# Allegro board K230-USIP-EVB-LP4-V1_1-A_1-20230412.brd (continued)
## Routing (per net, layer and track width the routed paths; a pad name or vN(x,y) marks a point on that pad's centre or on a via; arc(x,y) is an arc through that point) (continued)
DQ_B6: length 31.1
  TOP w0.086: v2(32.52,57.28) 32.6,57.28 U7.C4 ; U1.C19 v2(33.13,74.16)
  ART06 w0.086: v2(32.52,57.28) 32.13,57.68 32.13,58.75 31.75,59.13 31.75,62.93 31.84,63.02 32.77,63.02 32.92,63.17 32.92,63.4 32.65,63.67 32.65,65.32 32.49,65.48 31.84,65.48 31.7,65.62 31.7,65.82 31.84,65.96 32.49,65.96 32.63,66.1 32.63,66.3 32.49,66.44 31.84,66.44 31.7,66.58 31.7,66.78 31.84,66.92 32.49,66.92 32.63,67.06 32.63,67.26 32.49,67.4 31.84,67.4 31.7,67.54 31.7,67.74 31.84,67.88 32.49,67.88 32.63,68.02 32.63,68.17 32.49,68.31 31.84,68.31 31.7,68.46 31.7,68.65 31.84,68.79 32.49,68.79 32.63,68.94 32.63,69.18 32.49,69.32 31.74,69.32 31.62,69.44 31.62,69.7 31.73,69.8 32.36,69.8 32.5,69.94 32.5,70.14 32.36,70.28 31.43,70.28 31.29,70.43 31.29,70.62 31.43,70.76 32.23,70.76 32.37,70.91 32.37,71.1 32.23,71.24 31.54,71.24 31.39,71.39 31.39,71.6 31.54,71.74 32.49,71.74 32.63,71.88 32.63,72.3 33.13,72.8 v2(33.13,74.16)
DQ_B7: length 30.9
  TOP w0.086: U7.B4 32.6,57.93 v2(32.52,57.93) ; U1.B19 v2(33.77,74.16)
  ART06 w0.086: v2(32.52,57.93) 32.74,57.93 32.84,58.04 32.84,59.08 32.7,59.22 32.25,59.22 32.11,59.36 32.11,59.56 32.25,59.7 32.7,59.7 32.84,59.84 32.84,60.04 32.7,60.18 32.25,60.18 32.11,60.32 32.11,60.52 32.25,60.66 32.86,60.66 32.97,60.77 32.97,61.07 32.86,61.18 32.26,61.18 32.12,61.32 32.12,61.52 32.26,61.66 33.87,61.66 34.01,61.8 34.01,62 33.87,62.14 32.25,62.14 32.12,62.27 32.12,62.55 32.23,62.66 33.39,62.66 33.53,62.8 33.53,63.52 33.39,63.66 33.17,63.66 33.01,63.82 33.01,65.66 33.15,65.8 33.57,65.8 33.71,65.94 33.71,66.14 33.57,66.28 33.15,66.28 33.01,66.42 33.01,66.62 33.15,66.76 33.46,66.76 33.6,66.9 33.6,67.1 33.46,67.24 33.15,67.24 33.01,67.38 33.01,67.58 33.15,67.72 33.51,67.72 33.66,67.86 33.66,68.06 33.51,68.2 33.15,68.2 33.01,68.34 33.01,70.16 33.15,70.3 33.46,70.3 33.6,70.44 33.6,70.64 33.46,70.78 33.15,70.78 33.01,70.92 33.01,71.12 33.15,71.26 33.46,71.26 33.6,71.4 33.6,71.6 33.46,71.74 33.15,71.74 33.01,71.88 33.01,72.15 33.17,72.31 33.45,72.31 33.58,72.44 33.58,73.2 33.4,73.38 33.4,73.79 v2(33.77,74.16)
DQ_B8: length 35.4
  TOP w0.086: U1.D14 v2(33.13,77.41) ; U7.B11 38.6,57.61 v2(38.93,57.93)
  ART06 w0.086: v2(38.93,57.93) 40,57.93 43.28,61.21 43.28,62.81 45.31,64.85 45.31,67.28 44.17,68.43 44.17,68.73 44.31,68.87 45.15,68.87 45.29,69.01 45.29,69.21 45.15,69.35 44.26,69.35 44.12,69.49 44.12,69.69 44.26,69.83 44.69,69.83 44.83,69.97 44.83,70.17 44.69,70.31 44.31,70.31 44.17,70.45 44.17,70.88 43.97,71.08 43.77,71.08 43.69,70.99 43.49,70.99 43.35,71.13 43.35,71.33 43.43,71.42 43.43,71.62 37.33,77.72 35.56,77.72 35.23,78.05 34.24,78.05 33.92,77.74 33.45,77.74 v2(33.13,77.41)
DQ_B9: length 32.6
  TOP w0.086: U7.C11 38.6,56.96 v2(38.93,57.28) ; v2(36.92,78.04) 36.58,77.7 35.46,77.7 35.42,77.74 U1.A14
  ART06 w0.086: v2(38.93,57.28) 38.93,57.47 39.12,57.66 40.23,57.66 44.06,61.48 44.06,61.68 43.81,61.93 43.81,62.13 43.95,62.27 44.15,62.27 44.4,62.02 44.6,62.02 44.73,62.15 44.73,62.68 44.59,62.82 44.36,62.82 44.25,62.94 44.25,63.19 44.36,63.3 44.59,63.3 44.73,63.45 44.73,63.7 45.67,64.64 45.67,69.89 37.52,78.04 v2(36.92,78.04)
DQ_B10: length 33.7
  TOP w0.086: v2(35.7,78.06) 34.42,78.06 U1.B14 ; U7.E11 38.6,55.66 v2(38.93,55.98)
  ART06 w0.086: v2(35.7,78.06) 35.7,78.27 35.79,78.36 37.71,78.36 46.02,70.04 46.02,64.44 45.11,63.53 45.11,62.03 40.04,56.96 39.33,56.96 39.25,56.87 39.25,56.51 38.93,56.18 v2(38.93,55.98)
DQ_B11: length 35.3
  TOP w0.086: v2(33.78,78.06) 33.77,78.06 U1.C14 ; U7.F11 38.6,55.01 v2(38.93,55.33)
  ART06 w0.086: v2(38.93,55.33) 45.49,61.9 45.49,63.4 46.38,64.29 46.38,70.19 37.86,78.71 34.43,78.71 v2(33.78,78.06)
DQ_B12: length 32.7
  TOP w0.086: v2(37.33,54.68) 37.25,54.68 U7.F9 ; U1.B17 v2(33.77,76.11)
  ART06 w0.086: v2(33.77,76.11) 34.1,75.78 34.95,75.78 36.83,73.9 36.83,68.61 37.19,68.25 37.19,61.57 35.41,59.79 35.41,52.97 35.49,52.88 36.19,52.88 36.33,52.74 36.33,52.59 36.48,52.45 36.7,52.45 36.84,52.59 36.84,52.82 36.98,52.96 37.18,52.96 37.32,52.82 37.32,52.59 37.46,52.45 37.67,52.45 37.77,52.55 37.77,54.56 37.64,54.68 v2(37.33,54.68)
DQ_B13: length 33.8
  TOP w0.086: U7.E9 37,55.66 v2(37.33,55.33) ; U1.C16 v2(33.77,76.76)
  ART06 w0.086: v2(37.33,55.33) 37.33,55.11 37.24,55.02 36.18,55.02 36.09,55.1 36.09,55.58 36.18,55.66 36.87,55.66 36.96,55.75 36.96,59.39 37.78,60.21 39.56,60.21 40.64,61.29 40.64,61.8 38.25,64.19 38.25,68.76 37.9,69.11 37.9,69.85 38.63,70.59 39.6,70.59 39.88,70.87 39.88,72.44 39.01,73.3 38.76,73.3 38.61,73.46 38.61,73.79 36.28,76.11 35.52,76.11 35.19,76.44 34.09,76.44 v2(33.77,76.76)
DQ_B14: length 33.3
  TOP w0.086: v2(36.53,56.63) 36.6,56.63 U7.C9 ; v2(36.39,74.97) 35.57,74.97 U1.A17
  ART06 w0.086: v2(36.53,56.63) 36.25,56.36 35.99,56.36 35.81,56.54 35.81,56.92 36.11,57.21 36.11,58.01 35.81,58.31 35.81,59.69 37.06,60.93 37.43,60.93 37.57,61.08 37.57,61.28 37.71,61.42 38.87,61.42 39.01,61.28 39.01,61.08 39.1,60.99 39.29,60.99 39.6,61.29 39.6,61.8 39.47,61.93 37.69,61.93 37.54,62.08 37.54,68.43 37.19,68.78 37.19,71.75 37.34,71.91 37.54,71.91 37.68,71.77 37.68,71.46 37.76,71.37 38.07,71.37 38.16,71.46 38.16,71.82 38.3,71.96 38.5,71.96 38.63,71.83 38.63,71.46 38.72,71.37 39.03,71.37 39.12,71.46 39.12,72.19 38.91,72.39 38.56,72.39 38.3,72.64 38.08,72.64 37.82,72.39 37.59,72.39 37.19,72.8 37.19,74.17 v2(36.39,74.97)
DQ_B15: length 33.7
  TOP w0.086: U1.B16 v2(34.42,76.11) ; v2(36.53,57.28) 36.6,57.28 U7.B9
  ART06 w0.086: v2(36.53,57.28) 36.6,57.36 36.6,58.01 36.2,58.42 36.2,59.49 36.45,59.74 36.65,59.74 36.8,59.74 36.98,59.92 36.98,60.32 37.23,60.57 37.33,60.57 37.64,60.57 37.87,60.57 38.01,60.71 38.01,60.92 38.15,61.06 38.35,61.06 38.49,60.92 38.49,60.71 38.63,60.57 39.41,60.57 40.28,61.44 40.28,61.62 39.62,62.28 38.97,62.28 38.88,62.37 38.88,63.03 38.74,63.17 38.55,63.17 38.4,63.03 38.4,62.37 38.32,62.28 38,62.28 37.9,62.38 37.9,68.61 37.54,68.96 37.54,70 37.78,70.24 37.78,70.44 37.58,70.63 37.58,70.83 37.72,70.97 37.92,70.97 38.12,70.78 38.32,70.78 38.48,70.94 39.41,70.94 39.5,71.03 39.5,72.31 38.89,72.92 38.55,72.92 38.27,73.2 38.07,73.2 37.79,72.92 37.67,72.92 37.54,73.05 37.54,73.4 37.85,73.7 37.85,74.04 36.11,75.78 35.4,75.78 35.07,76.11 v2(34.42,76.11)
DQS0_C_A: length 30.7
  TOP w0.076: U1.Y17 22.19,75.79 22.08,75.67 v2(22.08,75.46)
  TOP w0.089: v2(19.02,55.98) 19.02,55.78 19.14,55.66 U5.E3
  ART06 w0.089: v2(22.08,75.46) 22.06,75.48 21.76,75.48 20.3,74.02 19.53,74.02 16.04,70.53 16.04,70.1 15.88,69.94 15.42,69.94 15.06,69.58 15.06,69.08 15.42,68.72 15.88,68.72 17.42,67.18 17.42,64.8 15.8,63.17 14.71,63.17 14.31,62.78 14.31,61.66 16.76,59.21 18.01,59.21 18.67,58.54 18.67,56.82 19.28,56.2 19.28,56.08 19.19,55.98 v2(19.02,55.98)
DQS0_C_B: length 31.1
  TOP w0.089: U1.A18 34.75,75.13 v2(34.43,74.81) ; U7.E3 32.05,55.66 v2(31.72,55.98)
  ART06 w0.089: v2(34.43,74.81) 34.43,74.52 34.54,74.4 34.54,73.9 34.7,73.75 35.03,73.75 35.38,73.39 35.38,72.88 35.03,72.53 34.7,72.53 34.54,72.38 34.54,72.15 34.7,71.99 35.03,71.99 35.38,71.64 35.38,71.13 35.03,70.78 34.7,70.78 34.54,70.62 34.54,70.39 34.7,70.24 35.03,70.24 35.38,69.89 35.38,69.38 35.03,69.02 34.7,69.02 34.54,68.87 34.54,68.64 34.7,68.49 35.03,68.49 35.38,68.14 35.38,67.62 35.03,67.27 34.7,67.27 34.54,67.12 34.54,66.89 34.7,66.74 35.16,66.74 35.48,66.41 35.48,65.9 35.11,65.52 34.7,65.52 34.54,65.37 34.54,65.14 34.7,64.98 35.36,64.98 35.71,64.63 35.71,64.12 35.36,63.76 34.7,63.76 34.54,63.61 34.54,63.29 34.7,63.14 35.39,63.14 35.75,62.78 35.75,62.19 33.78,60.22 33.78,56.21 33.29,55.71 32.32,55.71 32.05,55.98 v2(31.72,55.98)
DQS0_T_A: length 30.6
  TOP w0.076: U1.W17 v2(22.73,75.46)
  TOP w0.089: v2(19.82,55.98) 19.5,56.31 U5.D3
  ART06 w0.089: v2(22.73,75.46) 22.4,75.13 21.9,75.13 20.44,73.68 19.68,73.68 16.38,70.38 16.38,69.95 16.03,69.6 15.56,69.6 15.41,69.44 15.41,69.22 15.56,69.06 16.03,69.06 17.77,67.32 17.77,64.65 15.94,62.83 14.85,62.83 14.66,62.63 14.66,61.8 16.91,59.55 18.15,59.55 19.01,58.69 19.01,56.96 19.63,56.35 19.63,56.18 v2(19.82,55.98)
DQS0_T_B: length 31.3
  TOP w0.089: U1.B18 v2(33.78,74.81) ; v2(31.72,56.63) 32.05,56.31 U7.D3
  ART06 w0.089: v2(33.78,74.81) 34.08,74.5 34.08,74.38 34.2,74.26 34.2,73.76 34.55,73.4 34.89,73.4 35.04,73.25 35.04,73.02 34.89,72.87 34.55,72.87 34.2,72.52 34.2,72 34.55,71.65 34.89,71.65 35.04,71.5 35.04,71.27 34.89,71.12 34.55,71.12 34.2,70.77 34.2,70.25 34.55,69.9 34.89,69.9 35.04,69.75 35.04,69.52 34.89,69.37 34.55,69.37 34.2,69.01 34.2,68.5 34.55,68.15 34.89,68.15 35.04,67.99 35.04,67.77 34.89,67.61 34.55,67.61 34.2,67.26 34.2,66.75 34.55,66.39 35.01,66.39 35.14,66.27 35.14,66.04 34.96,65.86 34.55,65.86 34.2,65.51 34.2,64.99 34.55,64.64 35.22,64.64 35.37,64.49 35.37,64.26 35.22,64.11 34.55,64.11 34.2,63.75 34.2,63.15 34.55,62.79 35.25,62.79 35.41,62.63 35.41,62.33 33.44,60.36 33.44,57.33 33.33,57.22 33.23,57.22 33.12,57.12 33.12,56.97 33.23,56.87 33.33,56.87 33.44,56.76 33.44,56.35 33.15,56.06 32.46,56.06 32.19,56.33 31.89,56.33 31.72,56.49 v2(31.72,56.63)
DQS1_C_A: length 29.5
  TOP w0.089: v2(25.43,55.98) 25.1,55.66 U5.E10 ; U1.V19 v2(24.03,74.16)
  ART06 w0.089: v2(25.43,55.98) 25.12,55.98 24.79,56.31 23.67,56.31 23.48,56.5 23.48,61.19 23.13,61.54 22.7,61.54 22.54,61.7 22.54,61.92 22.7,62.08 23.13,62.08 23.48,62.44 23.48,62.94 23.13,63.3 22.7,63.3 22.54,63.45 22.54,63.67 22.7,63.83 23.13,63.83 23.48,64.19 23.48,64.69 23.13,65.05 22.7,65.05 22.54,65.21 22.54,65.43 22.7,65.58 23.13,65.58 23.48,65.94 23.48,66.45 23.13,66.8 22.7,66.8 22.54,66.96 22.54,67.18 22.7,67.34 23.13,67.34 23.48,67.69 23.48,68.2 23.13,68.56 22.7,68.56 22.54,68.71 22.54,68.93 22.7,69.09 23.13,69.09 23.48,69.45 23.48,69.95 23.13,70.31 22.7,70.31 22.54,70.46 22.54,70.69 22.7,70.84 23.95,70.84 24.35,71.23 24.35,73.84 v2(24.03,74.16)
DQS1_C_B: length 33.3
  TOP w0.089: U7.E10 37.8,55.66 v2(38.13,55.98) ; U1.A15 v2(34.42,77.41)
  ART06 w0.089: v2(34.42,77.41) 35.04,77.41 35.32,77.13 36.54,77.13 40.82,72.85 40.82,71.7 40.99,71.54 41.49,71.54 41.87,71.16 41.87,70.47 41.51,70.11 40.63,70.11 40.51,70 40.51,68.91 39.22,67.61 39.22,64.57 41.11,62.67 41.82,62.67 42.21,62.28 42.21,61.52 39.68,58.98 37.9,58.98 37.76,58.84 37.76,57.09 38.25,56.59 38.25,56.11 v2(38.13,55.98)
DQS1_T_A: length 29.1
  TOP w0.089: U1.V20 v2(24.03,73.51) ; v2(24.63,55.98) 24.95,56.31 U5.D10
  ART06 w0.089: v2(24.03,73.51) 24,73.49 24,73.42 23.9,73.32 23.78,73.32 23.67,73.21 23.67,73.06 23.78,72.96 23.9,72.96 24,72.86 24,71.38 23.81,71.18 22.56,71.18 22.2,70.83 22.2,70.32 22.56,69.97 22.98,69.97 23.14,69.81 23.14,69.59 22.98,69.43 22.56,69.43 22.2,69.07 22.2,68.57 22.56,68.21 22.98,68.21 23.14,68.06 23.14,67.84 22.98,67.68 22.56,67.68 22.2,67.32 22.2,66.82 22.56,66.46 22.98,66.46 23.14,66.3 23.14,66.08 22.98,65.93 22.56,65.93 22.2,65.57 22.2,65.06 22.56,64.71 22.98,64.71 23.14,64.55 23.14,64.33 22.98,64.17 22.56,64.17 22.2,63.82 22.2,63.31 22.56,62.95 22.98,62.95 23.14,62.8 23.14,62.58 22.98,62.42 22.56,62.42 22.2,62.06 22.2,61.56 22.56,61.2 22.98,61.2 23.14,61.05 23.14,56.36 23.53,55.97 23.84,55.97 23.95,55.86 23.95,55.76 24.05,55.65 24.2,55.65 24.3,55.76 24.3,55.86 24.41,55.97 24.61,55.97 v2(24.63,55.98)
DQS1_T_B: length 33.5
  TOP w0.089: U7.D10 37.65,56.31 v2(37.33,55.98) ; U1.B15 v2(34.43,76.76)
  ART06 w0.089: v2(34.43,76.76) 34.43,76.98 34.51,77.07 34.9,77.07 35.18,76.78 36.4,76.78 40.47,72.7 40.47,71.56 40.84,71.19 41.35,71.19 41.53,71.02 41.53,70.61 41.37,70.46 40.48,70.46 40.17,70.14 40.17,69.05 38.87,67.76 38.87,64.42 40.97,62.33 41.68,62.33 41.87,62.14 41.87,61.66 39.54,59.32 39.03,59.32 38.79,59.56 38.43,59.56 38.19,59.32 37.75,59.32 37.41,58.98 37.41,56.95 37.91,56.45 37.91,56.32 37.57,55.98 v2(37.33,55.98)
EMMC_CLK: length 36.7
  TOP w0.127: U1.A5 37.74,83.59 v2(38.1,83.95)
  BOTTOM w0.127: R50.1 38.73,109.35 41.4,106.68 41.4,94.13 41.25,93.99 40.53,93.99 40.39,93.84 40.39,93.63 40.53,93.48 41.25,93.48 41.4,93.33 41.4,93.12 41.25,92.97 40.53,92.97 40.39,92.82 40.39,92.61 40.53,92.46 41.25,92.46 41.4,92.31 41.4,92.02 41.25,91.87 40.56,91.87 40.39,91.69 40.39,88.14 38.48,86.23 38.48,84.33 v2(38.1,83.95)
EMMC_CMD: length 43
  TOP w0.127: v2(43.16,114.81) U30.M5 ; U1.D6 v2(33.12,83.26)
  BOTTOM w0.076: v2(33.12,83.26) 33.45,83.58 34.03,83.58
  BOTTOM w0.127: v2(43.16,114.81) 42.65,115.32 42.29,115.32 42.16,115.19 42.16,113.66 41.66,113.16 38.23,113.16 37.47,112.39 R48.1 37.97,111.89 38.1,111.76 38.1,109.35 39.12,108.33 39.12,103.12 38.1,102.11 38.1,97.03 35.69,94.61 35.69,89.66 36.45,88.9 36.45,85.09 34.94,83.58 34.03,83.58
EMMC_D0: length 43
  TOP w0.127: U1.D5 v2(33.12,83.91) ; U30.A3 44.16,109.13 44.32,108.97 44.32,107.19 42.55,105.41 39.75,105.41 38.73,104.39 38.73,104.01 v1(38.1,103.38)
  BOTTOM w0.076: v2(33.12,83.91) 33.45,84.23 34.03,84.23
  BOTTOM w0.127: v1(38.1,103.38) 37.34,102.62 37.34,97.28 34.16,94.11 32.03,94.11 31.88,93.95 31.88,93.74 32.03,93.59 32.89,93.59 33.02,93.46 33.02,93.19 32.89,93.07 32.03,93.07 31.88,92.91 31.88,92.7 32.03,92.54 32.99,92.54 33.15,92.39 33.15,92.18 32.99,92.02 32.03,92.02 31.88,91.87 31.88,91.66 32.03,91.5 32.99,91.5 33.15,91.35 33.15,90.3 33.27,90.17 34.8,90.17 34.92,90.04 34.92,89.03 35.43,88.52 35.43,85.34 34.32,84.23 34.03,84.23
EMMC_D1: length 43.1
  TOP w0.127: U30.A4 43.66,108.68 43.31,108.33 43.31,107.31 41.78,105.79 39.5,105.79 v1(38.1,104.39) ; U1.C5 v2(33.77,83.91)
  BOTTOM w0.127: v1(38.1,104.39) 38.61,104.39 38.73,104.27 38.73,103.25 37.72,102.23 37.72,97.16 35.31,94.74 35.31,93.62 35.15,93.46 33.68,93.46 33.53,93.31 33.53,93.1 33.68,92.94 35.15,92.94 35.31,92.79 35.31,92.58 35.15,92.42 33.68,92.42 33.53,92.27 33.53,92.05 33.68,91.9 35.15,91.9 35.31,91.75 35.31,91.53 35.15,91.38 33.68,91.38 33.53,91.23 33.53,91.01 33.68,90.86 35.15,90.86 35.31,90.71 35.31,89.41 35.94,88.77 35.94,85.34 34.51,83.91 v2(33.77,83.91)
EMMC_D2: length 43
  TOP w0.076: 35.05,83.91 34.42,83.91 U1.B5
  TOP w0.127: v2(38.1,84.71) 37.3,83.91 35.05,83.91 ; v1(40.64,106.55) 42.67,108.58 43.16,109.07 U30.A5
  BOTTOM w0.127: v1(40.64,106.55) 40.89,106.3 40.89,101.04 40.75,100.89 40.15,100.89 40.01,100.74 40.01,100.53 40.15,100.38 40.75,100.38 40.89,100.23 40.89,100.02 40.75,99.87 39.9,99.87 39.75,99.72 39.75,99.51 39.9,99.36 40.75,99.36 40.89,99.21 40.89,99 40.75,98.86 39.9,98.86 39.75,98.71 39.75,98.5 39.9,98.35 40.75,98.35 40.89,98.2 40.89,97.99 40.75,97.84 39.9,97.84 39.75,97.69 39.75,97.48 39.9,97.33 40.75,97.33 40.89,97.18 40.89,96.97 40.75,96.82 39.9,96.82 39.75,96.67 39.75,96.46 39.9,96.32 40.75,96.32 40.89,96.17 40.89,95.89 40.77,95.76 40.05,95.76 39.93,95.63 39.93,95.32 40.08,95.17 40.75,95.17 40.89,95.02 40.89,94.81 40.75,94.66 40.08,94.66 39.75,94.33 39.75,88.27 38.1,86.61 v2(38.1,84.71)
EMMC_D3: length 43
  TOP w0.076: 44.91,109.47 44.91,110.03 U30.B2
  TOP w0.127: v1(39.62,103.5) 41.91,103.5 45.09,106.68 45.09,109.09 44.91,109.27 44.91,109.47 ; U1.C6 v2(33.77,83.26)
  BOTTOM w0.127: v1(39.62,103.5) 39.62,103.12 38.48,101.98 38.48,96.9 37.08,95.5 37.08,94.67 36.93,94.52 36.22,94.52 36.07,94.37 36.07,94.15 36.22,94 37.06,94 37.21,93.85 37.21,93.63 37.06,93.48 36.22,93.48 36.07,93.33 36.07,93.11 36.22,92.96 36.93,92.96 37.08,92.81 37.08,92.59 36.93,92.44 36.22,92.44 36.07,92.29 36.07,92.07 36.22,91.92 36.93,91.92 37.08,91.77 37.08,91.55 36.93,91.4 36.22,91.4 36.07,91.25 36.07,91.03 36.22,90.88 36.93,90.88 37.08,90.72 37.08,90.51 36.93,90.36 36.22,90.36 36.07,90.2 36.07,89.99 36.22,89.84 36.83,89.84 36.96,89.71 36.96,84.96 35.25,83.26 v2(33.77,83.26)
EMMC_D4: length 43.3
  TOP w0.076: U30.B3 44.41,110.03 44.41,109.47
  TOP w0.127: v1(39.62,104.52) 42.29,104.52 44.7,106.93 44.7,108.97 44.41,109.26 44.41,109.47 ; U1.D7 v2(33.12,82.61)
  BOTTOM w0.076: 34.03,82.93 33.45,82.93 v2(33.12,82.61)
  BOTTOM w0.127: v1(39.62,104.52) 40.13,104.01 40.13,102.11 39.86,101.83 39.64,101.83 39.48,102 39.26,102 39.11,101.85 39.11,101.63 39.27,101.46 39.27,101.25 38.86,100.84 38.86,96.65 37.64,95.43 37.64,93.98 37.8,93.83 37.95,93.83 38.1,93.68 38.1,93.46 37.95,93.31 37.67,93.31 37.52,93.16 37.52,92.94 37.67,92.79 37.95,92.79 38.1,92.64 38.1,92.42 37.95,92.27 37.67,92.27 37.52,92.12 37.52,91.9 37.67,91.75 37.95,91.75 38.1,91.6 38.1,91.38 37.95,91.23 37.67,91.23 37.52,91.08 37.52,90.84 37.66,90.69 37.95,90.69 38.1,90.54 38.1,90.33 37.95,90.18 37.66,90.18 37.52,90.03 37.52,89.82 37.67,89.67 38.2,89.67 38.35,89.51 38.35,89.3 38.2,89.14 37.59,89.14 37.47,89.02 37.47,88.75 37.59,88.62 38.33,88.62 38.48,88.47 38.48,88.26 38.33,88.1 37.54,88.1 37.34,87.9 37.34,84.71 35.56,82.93 34.03,82.93
EMMC_D5: length 42.8
  TOP w0.076: 43.91,109.24 43.91,110.03 U30.B4
  TOP w0.127: U1.A7 35.55,82.29 35.61,82.35 38.79,82.35 39.26,82.82 39.51,82.82 v2(39.75,83.06) ; 43.91,109.24 43.91,107.66 v1(43.81,107.57)
  BOTTOM w0.127: v2(39.75,83.06) 40.13,83.44 40.13,85.22 41.27,86.36 42.16,86.36 43.43,87.63 43.43,101.98 43.56,102.11 45.19,102.11 45.34,102.26 45.34,102.48 45.19,102.63 43.59,102.63 43.43,102.78 43.43,103 43.59,103.15 45.19,103.15 45.34,103.3 45.34,103.52 45.19,103.67 44.58,103.67 44.45,103.8 44.45,104.06 44.58,104.19 45.19,104.19 45.34,104.34 45.34,107.44 45.21,107.57 v1(43.81,107.57)
EMMC_D6: length 43.1
  TOP w0.076: 43.41,109.24 43.41,110.03 U30.B5 ; 35.05,82.61 34.42,82.61 U1.B7
  TOP w0.127: 35.05,82.61 38.54,82.61 39.5,83.57 v2(39.5,83.95) ; 43.41,109.24 43.41,108.94 42.8,108.33 v1(42.8,107.7)
  BOTTOM w0.127: v1(42.8,107.7) 43.05,107.44 43.05,106.49 43.21,106.34 44.68,106.34 44.83,106.19 44.83,105.97 44.68,105.82 43.21,105.82 43.05,105.67 43.05,105.45 43.21,105.3 44.68,105.3 44.83,105.15 44.83,104.93 44.68,104.78 43.21,104.78 43.05,104.63 43.05,104.37 43.2,104.22 43.92,104.22 44.07,104.07 44.07,103.86 43.92,103.71 43.2,103.71 43.05,103.56 43.05,88.01 41.78,86.74 41.02,86.74 39.75,85.47 39.75,84.2 v2(39.5,83.95)
EMMC_D7: length 43
  TOP w0.076: U30.B6 42.91,110.03 42.91,109.47
  TOP w0.127: 42.91,109.47 42.91,109.33 42.42,108.84 42.04,108.84 v1(39.75,106.55) ; U1.C7 v2(33.77,82.61)
  BOTTOM w0.127: v1(39.75,106.55) 40.51,105.79 40.51,101.85 39.24,100.58 39.24,95.98 39.09,95.83 38.76,95.83 38.61,95.68 38.61,95.47 38.76,95.33 39.35,95.33 39.5,95.18 39.5,94.97 39.35,94.82 38.38,94.82 38.23,94.67 38.23,94.46 38.38,94.31 39.09,94.31 39.24,94.16 39.24,93.95 39.09,93.8 38.76,93.8 38.61,93.65 38.61,93.44 38.76,93.29 39.09,93.29 39.24,93.14 39.24,92.93 39.09,92.79 38.76,92.79 38.61,92.64 38.61,92.43 38.76,92.28 39.09,92.28 39.24,92.13 39.24,91.92 39.09,91.77 38.76,91.77 38.61,91.62 38.61,91.41 38.76,91.26 39.09,91.26 39.24,91.11 39.24,90.9 39.09,90.75 38.73,90.75 38.61,90.63 38.61,90.37 38.73,90.25 39.09,90.25 39.24,90.1 39.24,89.72 39.09,89.57 38.88,89.57 38.73,89.42 38.73,89.21 38.88,89.06 39.09,89.06 39.24,88.91 39.24,88.39 38.48,87.63 37.85,87.63 37.72,87.5 37.72,84.33 36.8,83.41 36.8,83.2 37.06,82.94 37.06,82.73 36.91,82.58 36.7,82.58 36.44,82.84 36.23,82.84 36.05,82.66 33.83,82.66 v2(33.77,82.61)
EMMC_RST: length 41.4
  TOP w0.127: U30.K5 v2(43.67,114.28) ; U1.A6 38.32,82.94 38.86,83.48 v2(38.86,83.99)
  BOTTOM w0.127: v2(38.86,83.99) 39.24,84.37 39.24,85.72 40.77,87.25 41.66,87.25 42.49,88.09 42.49,107.11 42.16,107.44 42.16,108.08 44.96,110.87 44.96,112.99 v2(43.67,114.28) R49.1 C25.1
EMMC_STROBE: length 40.1
  TOP w0.076: 34.92,83.26 34.42,83.26 U1.B6
  TOP w0.127: 34.92,83.26 38.05,83.26 38.48,83.69 38.48,84.33 v2(38.86,84.71)
  BOTTOM w0.127: R47.1 R59.1 40.01,108.84 40.47,108.37 40.69,108.37 41.17,108.85 41.39,108.85 41.54,108.7 41.54,108.49 41.06,108 41.06,107.79 41.91,106.93 41.91,91.31 41.78,91.19 41.15,91.19 41.02,91.06 41.02,90.91 41.17,90.76 41.76,90.76 41.91,90.61 41.91,90.4 41.76,90.25 41.17,90.25 41.02,90.1 41.02,89.89 41.17,89.75 41.76,89.75 41.91,89.6 41.91,89.39 41.76,89.24 41.17,89.24 41.02,89.09 41.02,88.14 38.86,85.98 v2(38.86,84.71)
FT_12MHZ_IN: length 8.2
  TOP w0.254: Y5.3 67.95,100.36 67.95,102 C201.1 67.89,102.7 67.89,103.69 66.35,105.23 U26.2
FT_12MHZ_OUT: length 7.2
  TOP w0.254: U26.3 66.48,105.73 68.39,103.83 68.39,102.71 C204.1 68.46,102.13 68.46,101.36 Y5.1
FTVCC_1V8: length 32.2
  TOP w0.254: v1(56.52,102.76) 56.96,103.2 U26.49 ; U26.64 v1(64.46,102.62) ; U26.12 66.15,110.23 v1(66.43,110.51) ; U26.37 v1(55.13,110.23)
  BOTTOM w0.381: v1(56.52,102.76) 56.65,102.89 C202.2 55.63,103.65 54.48,104.8 54.48,109.59 v1(55.13,110.23) 55.28,110.38 C221.2 ; C222.2 C220.2 ; C222.2 63.51,102.81 ; C222.2 68.09,103.65 69.34,104.9 69.34,109.86 68.69,110.51 v1(66.43,110.51) C199.2
FTVCC_3V3: length 21.4
  TOP w0.203: v1(53.72,110.87) 53.41,110.56 U36.1
  TOP w0.254: v1(57.74,102.76) 57.46,103.04 U26.50 ; U26.56 v1(60.46,102.77) ; v1(62.62,114.07) 62.96,113.72 U26.20 ; U26.31 v1(57.46,113.91) ; U26.42 v1(55.13,107.73)
  TOP w0.305: C368.1 53.98,111.12 v1(53.72,110.87)
  TOP w0.381: v1(64.77,98.17) R205.1 R204.1 R203.1 ; R201.1 v1(68.45,112.78)
  BOTTOM w0.305: C200.2 57.54,113.84 v1(57.46,113.91) ; v1(55.13,107.73) 55.24,107.84 C219.2 ; C203.2 v1(62.62,114.07)
  BOTTOM w0.381: v1(57.74,102.76) 57.54,102.97 C217.2 C216.2 ; FB7.1 v1(68.46,107.7) FB8.1 ; v1(60.46,102.77) 60.46,102.77 C218.2
  vias: v1(63.5,98.17) v1(69.72,112.78) v1(70.99,112.78)
G0: length 5.4
  TOP w0.127: TP28.1 R133.1 R131.1 57.02,125.73 57.42,125.33 U16.15
GPIO9: length 1.8
  TOP w0.127: R184.2 v1(9.02,81.92)
  BOTTOM w0.127: R184.2 v1(9.02,81.92)
GPIO26: length 6.6
  TOP w0.127: R91.1 5.08,27.94 3.17,27.94 J8.1
GPIO27: length 129.4
  TOP w0.127: R93.1 v1(6.22,73.91) ; v3(41.53,131.57) 41.26,131.85 J3.36
  ART06 w0.127: J8.2 3.43,30.23 3.43,47.24 4.39,48.21 4.39,53.49 5.73,54.83 5.73,73.42 v1(6.22,73.91) 6.73,74.42 6.73,75.44 5.73,76.44 5.73,77.74 7.23,79.24 7.23,84.52 8.36,85.65 12.88,85.65 20.83,93.6 20.83,117.73 33.15,130.05 40.01,130.05 v3(41.53,131.57)
GPIO28: length 132.2
  TOP w0.127: v3(42.67,132.59) 42.76,132.67 J3.42 ; R95.1 v1(6.22,75.06)
  ART06 w0.127: v3(42.67,132.59) 42.16,132.08 40.13,132.08 39.12,131.06 32.64,131.06 19.81,118.24 19.81,96.01 10.46,86.66 7.92,86.66 5.42,84.16 5.42,75.86 v1(6.22,75.06) 5.44,74.27 5.44,54.94 4.11,53.62 4.11,48.56 3.05,47.5 3.05,27.81 1.91,26.67
GPIO29: length 62.6
  TOP w0.127: R182.2 v1(8.89,84.45)
  ART06 w0.127: J8.4 5.46,27.69 5.46,29.84 3.71,31.6 3.71,47.02 4.7,48.01 4.7,53.37 6.02,54.69 6.02,69.09 8.08,71.15 8.08,83.64 v1(8.89,84.45)
  BOTTOM w0.127: R182.2 v1(8.89,84.45)
GPIO30: length 66.1
  TOP w0.127: R183.2 v1(8.89,83.19)
  ART06 w0.127: 1.91,24.13 3.17,25.4 5.08,25.4 5.84,26.16 5.84,29.97 3.99,31.83 3.99,46.66 5.08,47.75 5.08,53.34 6.3,54.56 6.3,68.96 8.38,71.04 8.38,82.68 v1(8.89,83.19)
  BOTTOM w0.127: R183.2 v1(8.89,83.19)
GPIO31: length 64.2
  TOP w0.127: R208.2 v1(8.89,80.77)
  ART06 w0.127: v1(8.89,80.77) 8.79,80.67 8.79,71.02 6.58,68.81 6.58,54.43 5.46,53.31 5.46,47.62 4.27,46.43 4.27,32.05 6.22,30.1 6.22,23.37 J8.8
  BOTTOM w0.127: R208.2 v1(8.89,80.77)
GPIO32: length 2.7
  TOP w0.127: R103.1 J8.6
GPIO33: length 6.2
  TOP w0.127: R105.1 5.97,22.73 3.05,22.73 1.91,21.59
GPIO34: length 6.3
  TOP w0.127: 1.91,19.05 3.17,20.32 5.84,20.32 R107.1
GPIO35: length 6.2
  TOP w0.127: 1.91,16.51 3.05,17.65 5.97,17.65 R109.1
GPIO36: length 6.2
  TOP w0.127: 1.91,13.97 3.05,15.11 5.97,15.11 R111.1
GPIO37: length 6.2
  TOP w0.127: 1.91,11.43 3.05,12.57 5.97,12.57 R113.1
GPIO42: length 36.2
  TOP w0.127: v1(36.83,104.14) 36.83,100.08 R100.2
  ART06 w0.127: v1(36.83,104.14) 37.21,104.52 37.21,117.86 47.16,127.8 v3(47.37,127.8)
  BOTTOM w0.127: R181.2 46.86,129.41 46.86,128.31 v3(47.37,127.8)
GPIO43: length 56.6
  TOP w0.127: R102.2 v1(49.28,84.07)
  ART06 w0.127: v3(49.4,127.8) 51.18,126.02 51.18,122.3 48.01,119.13 48.01,104.78 50.42,102.36 v1(51.18,102.36)
  BOTTOM w0.127: v1(49.28,84.07) 49.78,84.58 49.78,92.71 53.09,96.01 53.09,99.57 51.94,100.71 51.94,101.6 v1(51.18,102.36) ; R180.2 45.21,129.16 47.12,127.25 48.86,127.25 v3(49.4,127.8)
GPIO46: length 35.8
  ART06 w0.127: v1(38.1,105.41) 37.59,105.92 37.59,117.6 43.43,123.44 v1(44.58,123.44)
  BOTTOM w0.127: v1(44.58,123.44) 45.09,123.95 45.09,128.64 R179.2 ; R108.2 36.83,102.87 37.47,103.5 37.47,104.78 v1(38.1,105.41)
GPIO47: length 47.9
  TOP w0.127: J3.30 39.75,134.87 39.5,135.13 v3(39.24,135.13)
  ART06 w0.127: v3(39.24,135.13) 40.89,133.48 43.56,133.48 44.45,132.59 44.45,127 34.92,117.47 v1(34.92,109.73)
  BOTTOM w0.127: v1(34.92,109.73) 32,106.81 31.24,106.81 30.61,106.17 30.61,99.44 R110.2
GPIO48: length 46.6
  TOP w0.127: v3(40.13,135.06) 40.25,134.94 J3.32
  ART06 w0.127: v3(40.13,135.06) 41.4,133.79 43.88,133.79 44.83,132.84 44.83,126.75 35.56,117.47 35.56,107.19 v1(36.32,106.43)
  BOTTOM w0.127: R112.2 33.4,103.38 33.91,103.89 33.91,104.9 35.43,106.43 v1(36.32,106.43)
GPIO49: length 45.3
  TOP w0.127: J3.34 40.76,134.93 40.88,135.06 v3(40.89,135.06)
  ART06 w0.127: v1(36.32,107.44) 35.94,107.82 35.94,117.22 45.21,126.49 45.21,132.97 44.07,134.11 41.84,134.11 v3(40.89,135.06)
  BOTTOM w0.127: R114.2 35.69,103 36.32,103.63 36.32,104.65 37.08,105.41 37.08,106.68 v1(36.32,107.44)
GPIO52: length 104.3
  TOP w0.127: v1(51.31,107.19) 51.82,107.7 51.82,108.2 51.98,108.37 U36.6
  ART06 w0.127: v1(27.94,114.3) 26.16,114.3 25.4,113.54 25.4,103.63 v1(26.42,102.62)
  BOTTOM w0.127: v1(27.94,114.3) 31.11,117.47 45.34,117.47 48.9,113.92 48.9,109.6 v1(51.31,107.19) ; R119.1 26.42,102.49 v1(26.42,102.62) 23.24,102.62 19.37,98.74 19.37,79.69 10.79,71.12 5.97,71.12 5.45,71.63 5.45,73.92 J5.4 J5.2
GPIO53: length 137.7
  TOP w0.127: U36.5 51.74,108.77 v1(51.31,108.33)
  ART06 w0.127: v1(26.42,101.6) 25.02,103 25.02,113.86 26.48,115.32 v1(27.94,115.32) ; v1(74.42,84.45) 73.28,85.6 73.28,87.38 68.71,91.95 67.82,91.95 60.71,99.06 58.55,99.06 51.94,105.66 51.94,107.7 v1(51.31,108.33)
  BOTTOM w0.127: v1(51.31,108.33) 49.66,109.98 49.66,113.73 45.5,117.88 30.89,117.88 28.32,115.32 v1(27.94,115.32) ; v1(74.42,84.45) TVS12.1 73.55,83.58 R194.2 R55.2 ; J5.6 4.45,71.5 5.33,70.61 10.8,70.61 19.81,79.63 19.81,98.42 22.99,101.6 v1(26.42,101.6) 27.18,100.84 27.18,100.58 R120.1
GPIO60_3V3: length 69.6
  TOP w0.127: U25.12 69.3,118.19 v1(69.85,118.75) R242.2
  ART06 w0.127: v1(24.26,99.82) 23.5,100.58 23.5,114.94 v1(27.94,119.38)
  BOTTOM w0.127: R127.1 v1(24.26,99.82) ; v1(27.94,119.38) 27.94,119.38 46.48,119.38 49.02,116.84 63.88,116.84 64.52,116.2 65.79,116.2 68.33,118.75 v1(69.85,118.75)
GPIO61_3V3: length 69.1
  TOP w0.127: R243.2 70.1,116.97 v1(69.85,116.97) 69.47,116.97 68.64,117.79 U25.11
  ART06 w0.127: v1(27.94,118.37) 27.56,118.37 23.88,114.68 23.88,101.35 v1(25.4,99.82)
  BOTTOM w0.127: v1(69.85,116.97) 67.06,116.97 65.79,115.7 64.39,115.7 63.75,116.33 48.77,116.33 46.07,119.03 28.61,119.03 v1(27.94,118.37) ; v1(25.4,99.82) R128.1
HP_INSERT_DET: length 5.7
  TOP w0.127: J7.6 v1(76.2,124.33)
  BOTTOM w0.127: v1(76.2,124.33) 76.2,124.32 R35.2 ; R35.2 R221.2 ; R35.2 C162.1
HP_L: length 39.2
  TOP w0.127: J20.3 54.23,101.35 49.02,106.55 49.02,112.78 v1(51.05,114.81)
  ART06 w0.127: v1(66.55,122.56) 65.15,121.16 63.5,121.16 60.83,118.49 54.74,118.49 v1(51.05,114.81)
  BOTTOM w0.127: C159.1 v1(66.55,122.56)
HP_R: length 52.5
  TOP w0.127: J21.3 55.24,97.54 55.24,100.84 49.53,106.55 49.53,112.14 v1(51.05,113.67)
  ART06 w0.127: v1(51.05,113.67) 54.99,117.6 62.74,117.6 65.41,120.27 69.6,120.27 73.15,123.83 v1(73.15,126.11)
  BOTTOM w0.127: v1(73.15,126.11) 74.42,127.38 C161.1
HPOUTL: length 29.6
  TOP w0.127: U1.G1 30.85,88.89 43.31,101.35 v1(46.08,101.35)
  BOTTOM w0.127: J20.2 49.4,101.35 v1(46.08,101.35)
HPOUTR: length 31.3
  TOP w0.076: 31.18,86.47 31.18,85.86 U1.G2
  TOP w0.127: v1(46.08,100.33) 42.8,100.33 31.18,88.71 31.18,86.47
  BOTTOM w0.127: v1(46.08,100.33) 49.78,100.33 50.55,99.57 50.55,97.66 J21.2
HSY0: length 6.5
  TOP w0.127: J3.51 45.26,128.48 46.74,127 47.37,127 R51.2 R53.1
I2C0_SCL_1V8: length 75.2
  TOP w0.127: U25.3 64.16,118.19 63.1,117.13 63.1,115.86 62.32,115.08 56.37,115.08 v1(51.91,119.54) ; v3(41.66,135.06) 41.76,134.96 J3.38
  ART06 w0.127: v3(41.66,135.06) 42.31,134.4 45.81,134.4 53.09,127.13 53.09,120.72 v1(51.91,119.54)
  BOTTOM w0.127: J16.1 16.76,135.64 41.08,135.64 v3(41.66,135.06) 42.16,134.55 42.16,131.56 R234.2
I2C0_SDA_1V8: length 75.1
  TOP w0.127: U25.4 64.33,117.79 63.5,116.97 63.5,115.7 62.48,114.68 55.79,114.68 v1(51.93,118.55) ; J3.40 42.26,134.95 v3(42.42,135.12)
  ART06 w0.127: v1(51.93,118.55) 53.47,120.09 53.47,127.25 46,134.72 42.81,134.72 v3(42.42,135.12)
  BOTTOM w0.127: R235.2 43.31,131.43 43.31,134.23 v3(42.42,135.12) 42.42,136.53 42.04,136.91 18.03,136.91 J16.2
I2C1_SCL: length 40.4
  TOP w0.127: R240.2 43.92,128.17 v1(43.56,128.17) 43.26,128.47 J3.43 ; v1(35.81,104.2) 35.81,100.2 R96.2
  ART06 w0.127: v1(35.81,104.2) 33.66,106.36 33.66,119.13 42.7,128.17 v1(43.56,128.17)
I2C1_SDA: length 41.6
  TOP w0.127: J3.45 43.76,129.13 v1(43.94,128.94) 44.28,128.94 R241.2 ; R98.2 34.67,100.2 v1(34.67,104.2)
  ART06 w0.127: v1(34.67,104.2) 33.27,105.6 33.27,119.38 42.84,128.94 v1(43.94,128.94)
I2C3_SCL: length 38.2
  TOP w0.127: R104.2 37.34,99.44 37.34,104.39 v1(36.32,105.41) ; J3.41 42.76,128.19 v1(43.69,127.25) R239.2
  ART06 w0.127: v1(36.32,105.41) 34.42,107.31 34.42,117.98 v1(43.69,127.25)
I2C3_SDA: length 37
  TOP w0.127: J3.39 42.26,127.54 v1(42.61,127.19) R238.2
  ART06 w0.127: v1(35.31,105.41) 34.04,106.68 34.04,118.62 v1(42.61,127.19)
  BOTTOM w0.127: v1(35.31,105.41) 35.31,103.63 34.54,102.87 R106.2
I2C4_SCL: length 28.3
  TOP w0.127: v1(3.3,86.11) 3.05,86.36 3.05,89.66 5.8,92.41 J4.8 ; R77.1 v1(6.22,72.77)
  BOTTOM w0.127: v1(3.3,86.11) R7.1 R236.2 3.3,84.45 2.92,84.07 2.92,81.66 6.99,77.6 6.99,73.53 v1(6.22,72.77)
I2C4_SDA: length 28.1
  TOP w0.127: J4.9 5.81,92.91 2.67,89.77 2.67,84.71 v1(3.56,83.82) ; R79.1 v1(6.22,71.63)
  BOTTOM w0.127: v1(3.56,83.82) 3.81,83.82 R237.2 R74.1 4.45,80.64 7.37,77.72 7.37,72.77 v1(6.22,71.63)
JTAG_RST: length 53
  TOP w0.127: U1.V14 v2(24.03,77.41) ; 1.91,40.64 R206.2 5.21,41.27 5.71,41.78 v1(7.24,41.78)
  ART06 w0.127: v2(24.03,77.41) 17.63,77.41 12.83,72.61 12.83,70.99 9.91,68.07 9.91,44.45 v1(7.24,41.78)
JTAG_TCK: length 40.9
  TOP w0.076: 22.16,76.76 22.73,76.76 U1.W15
  TOP w0.127: v3(4.01,56.77) 5.21,56.77 16.13,67.69 16.13,73.28 19.22,76.37 21.17,76.37 21.57,76.76 22.16,76.76 ; R197.2 J12.3
  ART06 w0.127: J12.3 2.98,51.88 2.98,54.03 4.01,55.05 v3(4.01,56.77)
JTAG_TDI: length 46.8
  TOP w0.076: 22.04,77.41 23.38,77.41 U1.V15
  TOP w0.127: 1.91,45.72 R199.2 ; 22.04,77.41 19.21,77.41 15.24,73.44 15.24,68.41 v3(4.99,58.17)
  ART06 w0.127: 1.91,45.72 1.91,46.86 3.81,48.77 3.81,53.72 4.99,54.9 v3(4.99,58.17)
JTAG_TDO: length 44.3
  TOP w0.127: v3(4.01,58.17) 4.52,57.66 5.33,57.66 15.62,67.94 15.62,73.36 19.35,77.09 U1.Y15 ; R198.2 J12.4
  ART06 w0.127: J12.4 3.49,49.85 3.49,53.81 4.56,54.88 4.56,57.62 v3(4.01,58.17)
JTAG_TMS: length 53.1
  TOP w0.127: 1.91,43.18 R200.2 5.21,43.69 5.59,44.07 v1(7.24,44.07) ; U1.U14 v2(24.03,78.06)
  ART06 w0.076: 23.11,78.39 23.7,78.39 v2(24.03,78.06)
  ART06 w0.127: v1(7.24,44.07) 7.62,44.07 9.4,45.85 9.4,68.3 12.32,71.22 12.32,72.82 14.73,75.23 14.73,77.22 15.94,78.42 17.08,78.42 17.4,78.74 22.1,78.74 22.45,78.39 23.11,78.39
LCD_EN: length 32.7
  TOP w0.127: J4.29 3.09,102.91 0.83,100.65 0.83,83.25 3.3,80.77 R208.1
LCD_RST: length 31.2
  TOP w0.127: R184.1 6.48,81.28 3.68,81.28 1.33,83.63 1.33,100.39 3.35,102.41 J4.28
LDOFB: length 4.2
  TOP w0.254: U35.15 49.28,32.64 v1(48.77,33.15)
  BOTTOM w0.305: R282.2 R281.2 v1(48.77,33.15)
LDOIN: length 3.1
  TOP w0.254: R302.2 49.28,30.23 50.19,31.14 U35.18
LDOO: length 6.8
  TOP w0.254: U35.16 v1(48.77,32.14)
  TOP w0.305: R283.1 47.62,31.88 C349.1 47.88,32.14 v1(48.77,32.14)
  BOTTOM w0.381: v1(48.77,32.14) 48.76,32.13 C349.1
MICBIAS: length 83.3
  TOP w0.254: U1.E3 v2(32.47,85.21)
  TOP w0.305: v1(55.75,132.21) 52.45,128.91 52.45,125.09 46.48,119.13 46.48,105.16 v3(31.88,90.55) ; FB1.1 67.31,133.1 TVS13.1 v1(66.55,132.21)
  ART06 w0.305: v1(55.75,132.21) v1(66.55,132.21)
  BOTTOM w0.254: v3(31.88,90.55) 31.88,88.39 C153.1 C152.1 32.47,85.81 v2(32.47,85.21)
  BOTTOM w0.305: R31.1 75.44,131.7 67.06,131.7 v1(66.55,132.21)
MICNL: length 4.6
  TOP w0.102: 32.47,86.23 32.47,85.86 U1.E2
  TOP w0.127: 32.47,86.23 32.47,88.35 v3(33.15,89.03)
  BOTTOM w0.127: C154.1 32.89,88.77 v3(33.15,89.03)
MICNR: length 1
  TOP w0.127: U1.F2 v2(31.82,85.86)
  BOTTOM w0.127: C156.1 31.88,85.91 v2(31.82,85.86)
MICPL: length 77.9
  TOP w0.127: U1.E1 32.15,88.67 42.29,98.81 46.61,98.81 47.5,99.69 47.5,118.87 53.47,124.84 53.47,127.64 v1(55.75,129.92)
  ART06 w0.127: v1(71.63,130.81) 70.74,129.92 v1(55.75,129.92)
  BOTTOM w0.127: C157.1 75.26,130.81 v1(71.63,130.81)
MICPR: length 74.7
  TOP w0.127: C238.1 v1(71.63,132.46) ; U1.F1 31.5,88.52 42.29,99.31 46.35,99.31 46.99,99.95 46.99,118.87 52.96,124.84 52.96,128.14 v1(55.75,130.94)
  ART06 w0.127: v1(55.75,130.94) 70.1,130.94 v1(71.63,132.46)
MIPI_0V8: length 5.4
  TOP w0.254: U1.R8 v2(25.33,81.96) ; U1.N6 v2(26.63,83.26)
  ART03 w0.254: v2(26.63,83.26) 25.98,83.26
  ART06 w0.254: v2(25.33,81.96) v2(26.63,83.26)
  BOTTOM w0.254: C86.1 24.77,82.52 v2(25.33,81.96) ; C85.1 24.77,84.65 v2(24.68,84.56) ; v2(26.63,83.26) 26.32,83.57 C87.1
  vias: v1(54.48,41.27) v1(55.5,42.42) v1(55.5,41.27)
MIPI_1V8: length 37.3
  TOP w0.254: U1.R9 v2(25.33,81.31) ; U1.N7 v2(26.63,82.61)
  ART06 w0.254: v2(26.63,82.61) v2(25.33,81.31)
  ART06 w0.381: v1(44.96,38.99) 45.85,39.88 48.51,39.88 51.69,43.05 71.12,43.05 v1(72.14,44.07)
  BOTTOM w0.254: v2(19.58,76.71) C88.1 ; v2(26.63,82.61) 26.09,82.61 C90.1
  BOTTOM w0.381: R223.2 v1(72.14,44.07)
  vias: v1(44.7,41.66) v1(45.72,42.67) v1(45.72,41.78)
MIPI_RX0_CLK_N: length 88.2
  TOP w0.114: J3.1 32.75,129.3 32.84,129.21 32.84,128.58 32.62,128.36 30.02,128.36 29.82,128.56 29.82,129.9 29.42,130.3 28.85,130.3 28.45,129.9 28.45,128.56 28.25,128.36 27.97,128.36 27.77,128.56 27.77,129.9 27.36,130.3 26.8,130.3 26.39,129.9 26.39,128.56 26.19,128.36 25.91,128.36 25.71,128.56 25.71,129.9 25.31,130.3 24.74,130.3 24.34,129.9 24.34,128.56 24.14,128.36 23.85,128.36 23.65,128.56 23.65,129.9 23.25,130.3 22.68,130.3 22.28,129.9 22.28,128.56 22.08,128.36 21.79,128.36 21.59,128.56 21.59,129.9 21.19,130.3 20.62,130.3 20.22,129.9 20.22,128.56 20.02,128.36 19.56,128.36 19.36,128.56 19.36,129.9 18.96,130.3 18.39,130.3 17.99,129.9 17.99,128.56 17.79,128.36 16.49,128.36 13.5,125.36 13.5,117.17 13.88,116.79 15.03,116.79 15.28,116.55 15.28,116.28 15.1,116.11 13.93,116.11 13.5,115.68 13.5,100.71 18.53,95.68 18.53,91.86 20.74,89.65 20.74,88.52 20.55,88.33 20.55,88.07 20.74,87.88 20.74,86.88 22.1,85.52 22.38,85.52 U1.Y2
MIPI_RX0_CLK_P: length 88.2
  TOP w0.114: U1.W2 22.72,85.86 22.24,85.86 21.08,87.02 21.08,89.79 18.87,92 18.87,95.82 13.84,100.85 13.84,115.54 14.07,115.76 15.24,115.76 15.62,116.14 15.62,116.69 15.18,117.14 14.02,117.14 13.84,117.31 13.84,125.22 16.64,128.02 17.93,128.02 18.33,128.42 18.33,129.76 18.53,129.96 18.82,129.96 19.02,129.76 19.02,128.42 19.42,128.02 20.16,128.02 20.56,128.42 20.56,129.76 20.77,129.96 21.05,129.96 21.25,129.76 21.25,128.42 21.65,128.02 22.22,128.02 22.62,128.42 22.62,129.76 22.82,129.96 23.11,129.96 23.31,129.76 23.31,128.42 23.71,128.02 24.28,128.02 24.68,128.42 24.68,129.76 24.88,129.96 25.16,129.96 25.37,129.76 25.37,128.42 25.77,128.02 26.34,128.02 26.74,128.42 26.74,129.76 26.94,129.96 27.22,129.96 27.42,129.76 27.42,128.42 27.82,128.02 28.39,128.02 28.79,128.42 28.79,129.76 29,129.96 29.28,129.96 29.48,129.76 29.48,128.42 29.88,128.02 32.77,128.02 33.19,128.44 33.19,129.2 33.25,129.26 J3.3
MIPI_RX0_D0_N: length 88
  TOP w0.114: J3.4 33.25,132.31 31.97,131.03 31.97,129.69 31.57,129.29 31,129.29 30.6,129.69 30.6,132.43 30.4,132.63 30.11,132.63 29.91,132.43 29.91,131.5 29.51,131.1 28.94,131.1 28.54,131.5 28.54,132.43 28.34,132.63 28.05,132.63 27.85,132.43 27.85,131.5 27.45,131.1 26.88,131.1 26.48,131.5 26.48,132.43 26.28,132.63 26,132.63 25.8,132.43 25.8,131.5 25.39,131.1 24.83,131.1 24.42,131.5 24.42,132.43 24.22,132.63 23.94,132.63 23.74,132.43 23.74,131.5 23.34,131.1 20.42,131.1 20.02,131.5 20.02,132.3 19.82,132.5 19.53,132.5 19.33,132.3 19.33,131.5 18.93,131.1 18.07,131.1 12.66,125.69 12.66,100.48 17.78,95.36 17.78,89.39 17.98,89.19 18.26,89.19 18.99,89.92 19.56,89.92 19.96,89.51 19.96,88.95 19.23,88.22 19.23,87.93 19.81,87.35 19.81,87.07 21.67,85.21 22.72,85.21 U1.W3
MIPI_RX0_D0_P: length 88
  TOP w0.114: U1.Y3 22.38,84.87 21.53,84.87 19.47,86.93 19.47,87.21 18.89,87.79 18.89,88.36 19.62,89.09 19.62,89.37 19.42,89.57 19.13,89.57 18.4,88.85 17.83,88.85 17.44,89.24 17.44,95.22 12.32,100.34 12.32,125.83 17.93,131.44 18.79,131.44 18.99,131.65 18.99,132.44 19.39,132.84 19.96,132.84 20.36,132.44 20.36,131.65 20.56,131.44 23.2,131.44 23.4,131.65 23.4,132.57 23.8,132.97 24.37,132.97 24.77,132.57 24.77,131.65 24.97,131.44 25.25,131.44 25.45,131.65 25.45,132.57 25.85,132.97 26.42,132.97 26.82,132.57 26.82,131.65 27.03,131.44 27.31,131.44 27.51,131.65 27.51,132.57 27.91,132.97 28.48,132.97 28.88,132.57 28.88,131.65 29.08,131.44 29.37,131.44 29.57,131.65 29.57,132.57 29.97,132.97 30.54,132.97 30.94,132.57 30.94,129.83 31.14,129.63 31.42,129.63 31.63,129.83 31.63,131.17 32.1,131.65 32.1,131.93 32.29,132.11 32.57,132.11 32.91,132.46 32.91,133.08 32.75,133.24 J3.2
MIPI_RX0_D1_N: length 88.3
  TOP w0.114: U1.V1 23.72,86.2 23.72,86.76 22.19,88.29 22.19,88.69 22.32,88.82 22.55,88.82 22.68,88.96 22.68,89.15 22.55,89.28 22.32,89.28 22.19,89.42 22.19,90.21 19.96,92.43 19.96,96.28 14.99,101.26 14.99,108.29 15.19,108.49 16.24,108.49 16.64,108.89 16.64,109.46 16.24,109.86 15.19,109.86 14.99,110.06 14.99,110.35 15.19,110.55 18.27,110.55 18.67,110.95 18.67,111.52 18.27,111.92 15.19,111.92 14.99,112.12 14.99,112.41 15.19,112.61 19.03,112.61 19.43,113.01 19.43,113.58 19.03,113.98 15.19,113.98 14.99,114.18 14.99,114.46 15.19,114.66 17.89,114.66 18.41,115.19 18.41,115.91 14.99,119.34 14.99,124.71 17.18,126.91 34.05,126.91 34.67,127.53 34.67,129.16 34.75,129.24 J3.9
MIPI_RX0_D1_P: length 88.4
  TOP w0.114: J3.7 34.25,129.24 34.33,129.16 34.33,127.68 33.91,127.25 17.04,127.25 14.64,124.86 14.64,119.2 18.07,115.77 18.07,115.33 17.75,115.01 15.04,115.01 14.64,114.61 14.64,114.04 15.04,113.64 18.89,113.64 19.09,113.43 19.09,113.15 18.89,112.95 15.04,112.95 14.64,112.55 14.64,111.98 15.04,111.58 18.13,111.58 18.33,111.38 18.33,111.09 18.13,110.89 15.04,110.89 14.64,110.49 14.64,109.92 15.04,109.52 16.09,109.52 16.29,109.32 16.29,109.04 16.09,108.84 15.04,108.84 14.64,108.43 14.64,101.11 19.62,96.14 19.62,92.29 21.84,90.07 21.84,88.14 23.37,86.61 23.37,85.86 U1.V2
MIPI_RX1_CLK_N: length 88.1
  TOP w0.114: J3.14 35.75,134.89 35.83,134.97 35.83,135.64 34.66,136.82 34.32,136.82 34.19,136.68 34.19,136.53 34.05,136.4 33.86,136.4 33.73,136.53 33.73,136.68 33.6,136.82 33.41,136.82 33.27,136.68 33.27,136.53 33.14,136.4 32.95,136.4 32.82,136.53 32.82,136.68 32.68,136.82 23.23,136.82 23.03,136.62 23.03,135.15 22.63,134.75 22.06,134.75 21.66,135.15 21.66,136.64 21.43,136.87 20.6,136.87 20.32,136.58 20.32,136.3 20.81,135.81 20.81,135.24 20.41,134.84 19.84,134.84 19.35,135.33 18.94,135.33 10.34,126.73 10.34,99.14 15.11,94.36 15.11,89.26 20.46,83.91 22.72,83.91 U1.W5
MIPI_RX1_CLK_P: length 88
  TOP w0.114: J3.16 36.25,134.89 36.18,134.97 36.18,135.78 34.8,137.16 23.09,137.16 22.68,136.76 22.68,135.29 22.48,135.09 22.2,135.09 22,135.29 22,136.78 21.57,137.21 20.46,137.21 19.98,136.73 19.98,136.16 20.47,135.66 20.47,135.38 20.27,135.18 19.98,135.18 19.49,135.67 18.8,135.67 9.99,126.87 9.99,98.99 14.77,94.22 14.77,89.12 20.32,83.57 22.38,83.57 U1.Y5
MIPI_RX1_D2_N: length 88.3
  TOP w0.114: J3.10 34.75,134.89 34.67,134.97 34.67,135.32 34.36,135.64 30.72,135.64 30.26,135.18 30.26,134.25 30.08,134.07 29.6,134.07 29.4,134.27 29.4,135.49 29,135.89 28.43,135.89 28.03,135.49 28.03,134.27 27.83,134.07 27.55,134.07 27.35,134.27 27.35,135.49 26.94,135.89 26.38,135.89 25.97,135.49 25.97,134.27 25.77,134.07 25.49,134.07 25.29,134.27 25.29,135.49 24.89,135.89 24.32,135.89 23.92,135.49 23.92,134.27 23.72,134.07 22.65,134.07 22.25,133.67 22.25,132.75 22.05,132.55 21.77,132.55 21.56,132.75 21.56,133.67 21.16,134.07 18.94,134.07 11.09,126.22 11.09,99.78 16.13,94.74 16.13,88.97 20.88,84.22 22.38,84.22 U1.Y4
MIPI_RX1_D2_P: length 88.2
  TOP w0.114: U1.W4 22.72,84.56 21.03,84.56 16.47,89.12 16.47,94.88 11.43,99.93 11.43,126.08 19.08,133.73 21.02,133.73 21.22,133.53 21.22,132.61 21.62,132.21 22.19,132.21 22.59,132.61 22.59,133.53 22.79,133.73 23.86,133.73 24.26,134.13 24.26,135.35 24.46,135.55 24.74,135.55 24.95,135.35 24.95,134.13 25.35,133.73 25.92,133.73 26.32,134.13 26.32,135.35 26.52,135.55 26.8,135.55 27,135.35 27,134.13 27.4,133.73 27.97,133.73 28.37,134.13 28.37,135.35 28.58,135.55 28.86,135.55 29.06,135.35 29.06,134.13 29.46,133.73 30.23,133.73 30.61,134.11 30.61,135.04 30.86,135.29 31.26,135.29 31.4,135.16 31.4,134.86 31.53,134.72 31.72,134.72 31.85,134.86 31.85,135.16 31.99,135.29 34.22,135.29 34.33,135.18 34.33,134.97 34.25,134.89 J3.8
MIPI_RX1_D3_N: length 87.9
  TOP w0.114: U1.W6 22.72,83.26 19.86,83.26 13.72,89.41 13.72,93.98 9.23,98.46 9.23,127.11 20.08,137.96 35.39,137.96 35.75,137.61 35.75,137.4 35.71,137.35 35.71,137.14 35.85,136.99 36.07,136.99 36.11,137.04 36.32,137.04 36.47,136.89 36.47,136.68 36.42,136.63 36.42,136.42 36.57,136.27 36.78,136.27 36.83,136.32 37.04,136.32 37.41,135.94 37.41,135.05 37.25,134.89 J3.20
MIPI_RX1_D3_P: length 88
  TOP w0.114: U1.Y6 22.38,82.92 19.72,82.92 13.37,89.27 13.37,93.84 8.89,98.32 8.89,127.26 19.94,138.3 35.54,138.3 37.75,136.09 J3.22
MIPI_RX2_CLK_N: length 88.3
  TOP w0.114: J3.25 38.75,129.24 38.83,129.16 38.83,128.43 42.16,125.1 42.16,118.34 41.81,117.98 35.56,117.98 34.16,119.38 34.16,123.19 33.57,123.79 18.53,123.79 18.03,123.29 18.03,120.55 22.9,115.68 22.9,110.78 22.32,110.2 22.32,109.63 22.47,109.48 22.47,109.19 22.27,108.99 21.99,108.99 21.83,109.15 21.26,109.15 18.03,105.92 18.03,102.37 23.24,97.17 23.24,93.73 25.32,91.64 25.32,85.86 U1.R2
MIPI_RX2_CLK_P: length 88.4
  TOP w0.114: U1.R1 25.67,86.2 25.67,91.79 25.1,92.35 25.1,92.54 25.17,92.62 25.17,92.81 25.04,92.94 24.85,92.94 24.77,92.87 24.58,92.87 24.45,93 24.45,93.19 24.53,93.27 24.53,93.46 24.39,93.59 24.2,93.59 24.13,93.51 23.94,93.51 23.58,93.87 23.58,97.31 18.38,102.52 18.38,105.78 21.41,108.8 21.69,108.8 21.85,108.65 22.41,108.65 22.82,109.05 22.82,109.62 22.66,109.77 22.66,110.06 23.24,110.64 23.24,115.82 18.38,120.69 18.38,123.15 18.67,123.44 33.42,123.44 33.82,123.05 33.82,119.24 35.42,117.64 41.95,117.64 42.51,118.2 42.51,125.24 39.18,128.57 39.18,129.16 39.25,129.24 J3.27
MIPI_RX2_D4_N: length 88.3
  TOP w0.114: U1.T1 25.02,86.2 25.02,90.66 24.69,90.99 24.69,91.18 24.74,91.23 24.74,91.42 24.6,91.55 24.41,91.55 24.36,91.5 24.17,91.5 24.04,91.64 24.04,91.82 24.09,91.88 24.09,92.06 23.96,92.2 23.77,92.2 23.72,92.15 23.53,92.15 22.15,93.53 22.15,97.2 17.27,102.07 17.27,106.3 21.84,110.87 21.84,115.67 17.27,120.24 17.27,123.7 18.16,124.59 34.19,124.59 34.96,123.81 34.96,119.85 36.03,118.78 38.34,118.78 38.74,119.18 38.74,119.6 38.94,119.8 39.23,119.8 39.43,119.6 39.43,119.18 39.83,118.78 40.78,118.78 41.24,119.24 41.24,124.88 37.68,128.44 37.68,129.17 37.75,129.24 J3.21
MIPI_RX2_D4_P: length 88.4
  TOP w0.114: U1.T2 24.67,85.86 24.67,90.52 21.81,93.38 21.81,97.05 16.93,101.93 16.93,106.44 21.5,111.01 21.5,115.53 16.93,120.1 16.93,123.84 18.02,124.93 34.33,124.93 35.31,123.95 35.31,119.99 36.17,119.13 38.2,119.13 38.4,119.33 38.4,119.74 38.8,120.14 39.37,120.14 39.77,119.74 39.77,119.33 39.97,119.13 40.64,119.13 40.89,119.38 40.89,124.74 37.34,128.29 37.34,129.16 37.25,129.24 J3.19
MIPI_RX2_D5_N: length 88.3
  TOP w0.114: U1.U2 24.02,85.86 24.02,87.48 23.39,88.11 23.39,90.17 20.71,92.85 20.71,96.59 15.79,101.52 15.79,106.95 20.32,111.48 20.32,115.16 15.79,119.7 15.79,124.35 17.55,126.11 35.66,126.11 36.58,125.2 36.58,123.84 36.78,123.64 38.08,123.64 38.48,123.24 38.48,122.67 38.08,122.27 36.78,122.27 36.58,122.07 36.58,121.64 36.85,121.37 39.48,121.37 39.75,121.64 39.75,124.23 35.83,128.15 35.83,129.16 35.75,129.24 J3.13
MIPI_RX2_D5_P: length 88.4
  TOP w0.114: J3.15 36.25,129.24 36.18,129.16 36.18,128.29 40.09,124.37 40.09,121.5 39.62,121.03 36.7,121.03 36.23,121.5 36.23,122.21 36.63,122.61 37.94,122.61 38.14,122.81 38.14,123.1 37.94,123.3 36.63,123.3 36.23,123.7 36.23,125.06 35.52,125.77 17.69,125.77 16.13,124.21 16.13,119.84 20.66,115.31 20.66,111.34 16.13,106.81 16.13,101.66 21.06,96.74 21.06,92.99 23.87,90.18 23.97,90.18 24.1,90.04 24.1,89.85 23.97,89.72 23.87,89.72 23.74,89.58 23.74,89.4 23.87,89.26 23.97,89.26 24.1,89.13 24.1,88.94 23.97,88.8 23.87,88.8 23.74,88.67 23.74,88.25 24.37,87.62 24.37,86.2 U1.U1
MIPI_TX0_CLK_N: length 38.9
  TOP w0.114: U1.W9 22.72,81.31 17.88,81.31 16.38,82.8 15.75,82.8 14.57,83.99 14.57,84.21 14.68,84.33 v3(15.07,84.33) ; J4.19 7.18,97.91 7.1,97.99 6.29,97.99 6.17,97.87 v3(6.17,97.65)
  BOTTOM w0.114: v3(15.07,84.33) 14.86,84.33 14.64,84.1 14.64,83.94 14.86,83.72 15.37,83.72 15.88,84.22 15.88,84.96 15.74,85.09 15.5,85.09 15.37,85.22 15.37,85.41 15.5,85.55 15.74,85.55 15.88,85.68 15.88,87.76 10.16,93.47 10.16,95.26 9.96,95.46 8.53,95.46 8.13,95.87 8.13,96.43 8.53,96.84 9.96,96.84 10.16,97.04 10.16,97.66 9.82,98.01 6.53,98.01 v3(6.17,97.65)
MIPI_TX0_CLK_P: length 38.9
  TOP w0.114: J4.20 7.18,98.41 7.1,98.33 6.51,98.33 v3(6.17,98.67) ; v3(14.18,84.33) 14.22,84.28 14.22,83.84 15.61,82.46 16.24,82.46 17.73,80.97 22.38,80.97 U1.Y9
  BOTTOM w0.114: v3(14.18,84.33) 14.29,84.21 14.29,83.8 14.72,83.37 15.51,83.37 16.22,84.08 16.22,87.9 10.5,93.61 10.5,95.41 10.1,95.81 8.67,95.81 8.47,96.01 8.47,96.29 8.67,96.49 10.1,96.49 10.5,96.9 10.5,97.81 9.96,98.35 6.49,98.35 v3(6.17,98.67)
MIPI_TX0_D0_N: length 39
  TOP w0.114: J4.22 7.18,99.41 7.02,99.57 2.85,99.57 2.74,99.45 v3(2.74,99.24) ; U1.Y10 22.38,80.32 17.24,80.32 16.37,81.19 14.21,81.19 12.46,82.94 12.46,84.19 12.32,84.33 v3(12.15,84.33)
  BOTTOM w0.114: v3(12.15,84.33) 12.33,84.33 12.45,84.44 12.45,84.73 12.05,85.13 11.52,85.13 6.69,89.95 6.21,89.95 5.52,90.64 5.52,92.77 3.98,94.32 3.98,99.04 3.32,99.69 2.85,99.69 2.74,99.58 v3(2.74,99.24)
MIPI_TX0_D0_P: length 39.1
  TOP w0.114: U1.W10 22.72,80.66 17.38,80.66 16.51,81.53 14.35,81.53 12.8,83.08 12.8,84.09 v3(13.04,84.33) ; J4.23 3.09,99.91 v3(2.74,100.26)
  BOTTOM w0.114: v3(2.74,100.26) 2.96,100.04 3.47,100.04 4.32,99.19 4.32,94.47 5.87,92.92 5.87,90.78 6.35,90.3 6.84,90.3 11.66,85.47 12.19,85.47 12.79,84.87 12.79,84.58 v3(13.04,84.33)
MIPI_TX0_D1_N: length 38.7
  TOP w0.114: v3(3.25,96.26) 3.48,96.49 7.13,96.49 7.2,96.41 J4.16 ; v3(11,84.33) 10.88,84.33 10.77,84.21 10.77,83.21 13.97,80.01 22.72,80.01 U1.W11
  BOTTOM w0.114: v3(11,84.33) 10.8,84.33 10.67,84.46 10.67,84.96 7.79,87.85 6.97,87.85 6.37,87.24 6.1,87.24 5.88,87.46 5.88,87.73 6.16,88.01 6.16,88.58 4.78,89.97 4.78,92.36 2.41,94.72 2.41,96.39 2.58,96.56 3.13,96.56 3.25,96.44 v3(3.25,96.26)
MIPI_TX0_D1_P: length 38.8
  TOP w0.114: J4.17 7.2,96.91 7.13,96.83 3.56,96.83 v3(3.25,97.15) ; U1.Y11 22.38,79.67 13.83,79.67 10.43,83.07 10.43,84.02 v3(10.12,84.33)
  BOTTOM w0.114: v3(10.12,84.33) 10.33,84.54 10.33,84.82 7.64,87.5 7.11,87.5 6.51,86.9 5.96,86.9 5.54,87.32 5.54,87.87 5.82,88.15 5.82,88.44 4.43,89.82 4.43,92.21 2.07,94.58 2.07,96.54 2.44,96.9 3,96.9 v3(3.25,97.15)
MIPI_TX1_D2_N: length 39
  TOP w0.114: U1.Y8 22.38,81.62 18.46,81.62 14.8,85.28 8.83,85.28 8.25,85.86 8.25,86.43 8.85,87.03 8.85,87.31 8.64,87.52 8.36,87.52 7.76,86.92 7.19,86.92 5.84,88.27 3.87,88.27 3.76,88.15 v3(3.76,87.91) ; v3(2.16,92.16) 2.16,92.27 2.27,92.38 2.69,92.38 5.38,95.07 5.76,95.07 5.96,94.87 6.22,94.87 6.42,95.07 7.05,95.07 7.2,94.91 J4.13
  BOTTOM w0.114: v3(2.16,92.16) 2.16,92.28 2.26,92.38 2.58,92.38 2.71,92.25 2.71,89.84 2.5,89.64 1.93,89.64 1.52,89.24 1.52,88.67 1.93,88.27 3.64,88.27 3.76,88.15 v3(3.76,87.91)
MIPI_TX1_D2_P: length 38.9
  TOP w0.114: J4.14 5.24,95.41 2.55,92.72 2.36,92.72 v3(2.16,92.92) ; U1.W8 22.72,81.96 18.6,81.96 14.94,85.62 8.97,85.62 8.59,86 8.59,86.29 9.19,86.89 9.19,87.46 8.79,87.86 8.22,87.86 7.62,87.26 7.33,87.26 5.98,88.61 3.95,88.61 v3(3.76,88.8)
  BOTTOM w0.114: v3(2.16,92.92) 2.36,92.72 2.72,92.72 3.05,92.4 3.05,89.7 2.65,89.29 2.07,89.29 1.87,89.09 1.87,88.81 2.07,88.61 3.56,88.61 v3(3.76,88.8)
MIPI_TX1_D3_N: length 38.8
  TOP w0.114: J4.25 7.18,100.91 7.1,100.99 6.51,100.99 v3(6.17,100.65) ; U1.W7 22.72,82.61 19.24,82.61 14.97,86.88 13.15,86.88 v3(12.7,87.33)
  BOTTOM w0.114: v3(12.7,87.33) 12.49,87.12 12.06,87.12 11.94,87.25 11.94,87.79 11.54,88.19 10.83,88.19 10.63,88.39 10.63,88.67 10.83,88.87 11.54,88.87 11.94,89.28 11.94,89.92 9.86,91.99 9.29,91.99 8.25,90.95 7.96,90.95 7.76,91.15 7.76,91.43 8.81,92.48 8.81,93.05 8.26,93.6 6.84,93.6 5.56,94.87 5.56,100.87 5.78,101.09 6.06,101.09 6.17,100.98 v3(6.17,100.65)
MIPI_TX1_D3_P: length 38.8
  TOP w0.114: v3(12.7,86.32) 12.92,86.54 14.83,86.54 19.1,82.27 22.38,82.27 U1.Y7 ; v3(6.17,101.67) 6.51,101.33 7.1,101.33 7.18,101.41 J4.26
  BOTTOM w0.114: v3(6.17,101.67) 5.94,101.43 5.64,101.43 5.22,101.01 5.22,94.73 6.69,93.26 8.11,93.26 8.46,92.9 8.46,92.62 7.42,91.57 7.42,91.01 7.82,90.6 8.39,90.6 9.44,91.65 9.72,91.65 11.6,89.77 11.6,89.42 11.39,89.22 10.69,89.22 10.29,88.82 10.29,88.25 10.69,87.85 11.39,87.85 11.6,87.64 11.6,87.11 11.92,86.78 12.24,86.78 v3(12.7,86.32)
MMC1_CLK: length 65.1
  TOP w0.127: U4.5 67.2,86.09 v1(68.07,85.22) ; R122.1 29.97,100.08 v1(31.37,100.08)
  ART06 w0.127: v1(31.37,100.08) 35.68,95.76 35.68,95.55 34.94,94.81 34.94,94.6 35.09,94.45 35.3,94.45 36.04,95.19 36.25,95.19 36.4,95.04 36.4,94.83 35.66,94.09 35.66,93.88 35.81,93.73 36.02,93.73 36.76,94.47 36.97,94.47 37.12,94.32 37.12,94.11 36.38,93.37 36.38,93.16 36.53,93.01 36.74,93.01 37.48,93.75 37.69,93.75 37.84,93.6 37.84,93.39 37.1,92.65 37.1,92.44 37.25,92.29 37.46,92.29 38.2,93.04 38.41,93.04 38.56,92.89 38.56,92.68 37.82,91.93 37.82,91.72 37.97,91.57 38.18,91.57 38.92,92.32 39.13,92.32 39.28,92.17 39.28,91.96 38.79,91.47 38.79,91.26 38.94,91.11 39.15,91.11 39.64,91.6 39.85,91.6 40.3,91.15 56.81,91.15 57.4,90.55 64.01,90.55 68.07,86.49 v1(68.07,85.22)
  BOTTOM w0.127: R188.2 68.2,85.09 v1(68.07,85.22) U22.3
MMC1_CMD: length 64.4
  TOP w0.127: v1(68.2,87.63) 67.54,88.29 U4.3 ; v1(32.64,100.08) 32.26,100.08 R121.1
  ART06 w0.127: v1(68.2,87.63) 67.69,87.63 63.5,91.82 60.29,91.82 60.13,91.97 60.13,92.94 59.98,93.09 59.77,93.09 59.61,92.94 59.61,91.72 59.46,91.57 59.25,91.57 59.09,91.72 59.09,92.94 58.94,93.09 58.72,93.09 58.57,92.94 58.57,91.72 58.42,91.57 58.2,91.57 58.05,91.72 58.05,92.94 57.9,93.09 57.68,93.09 57.53,92.94 57.53,91.97 57.38,91.82 57.16,91.82 57.01,91.97 57.01,92.94 56.86,93.09 56.64,93.09 56.49,92.94 56.49,91.97 56.34,91.82 56.12,91.82 55.97,91.97 55.97,92.94 55.82,93.09 55.6,93.09 55.45,92.94 55.45,91.97 55.3,91.82 55.08,91.82 54.93,91.97 54.93,92.94 54.78,93.09 54.56,93.09 54.41,92.94 54.41,91.97 54.25,91.82 54.04,91.82 53.89,91.97 53.89,92.94 53.73,93.09 53.52,93.09 53.37,92.94 53.37,91.85 53.17,91.66 41.06,91.66 v1(32.64,100.08)
  BOTTOM w0.127: R162.2 v1(68.2,87.63) 68.07,87.5 U22.2
